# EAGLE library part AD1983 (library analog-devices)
HD Audio SoundMAX® Codec Auto generated by make-symbol-device-package-bsdl.ulp Rev. 33 Source: http://www.analog.com/static/imported-files/data_sheets/AD1983.pdf
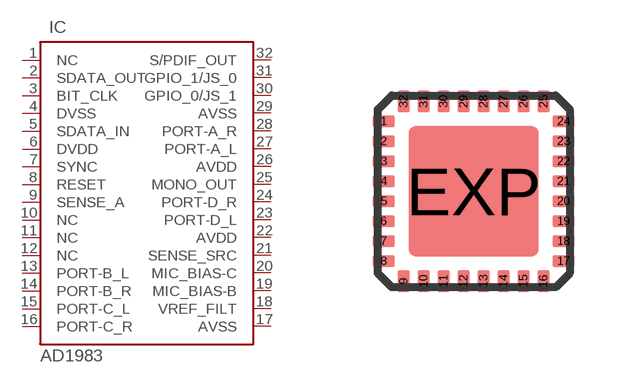
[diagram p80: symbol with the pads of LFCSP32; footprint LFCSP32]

Designator prefix IC

## AD1983 (OC_FARNELL: unknown; OC_NEWARK: unknown)  [LFCSP32]
1  NC  nc
2  SDATA_OUT  in
3  BIT_CLK  in
4  DVSS  pwr
5  SDATA_IN
6  DVDD  pwr
7  SYNC  in
8  RESET  in
9  SENSE_A  in
10  NC  nc
11  NC  nc
12  NC  nc
13  PORT-B_L  in
14  PORT-B_R  in
15  PORT-C_L  in
16  PORT-C_R  in
17  AVSS  pwr
18  VREF_FILT  out
19  MIC_BIAS-B  out
20  MIC_BIAS-C  out
21  SENSE_SRC  out
22  AVDD  pwr
23  PORT-D_L  out
24  PORT-D_R  out
25  MONO_OUT  out
26  AVDD  in
27  PORT-A_L  out
28  PORT-A_R  out
29  AVSS  pwr
30  GPIO_0/JS_1
31  GPIO_1/JS_0
32  S/PDIF_OUT  out

## Footprint LFCSP32 (pad centres in mm)
32-Lead Frame Chip Scale Package [LFCSP_VQ] 5 mm × 5 mm Very Thin Quad (CP-32-3 COMPLIANT TO JEDEC STANDARDS MO-220-VHHD-2 Source: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
smd 0.55 x 0.3: 1 -2.25,1.75; 2 -2.25,1.25; 3 -2.25,0.75; 4 -2.25,0.25; 5 -2.25,-0.25; 6 -2.25,-0.75; 7 -2.25,-1.25; 8 -2.25,-1.75; 17 2.25,-1.75; 18 2.25,-1.25; 19 2.25,-0.75; 20 2.25,-0.25; 21 2.25,0.25; 22 2.25,0.75; 23 2.25,1.25; 24 2.25,1.75
smd 0.3 x 0.55: 9 -1.75,-2.25; 10 -1.25,-2.25; 11 -0.75,-2.25; 12 -0.25,-2.25; 13 0.25,-2.25; 14 0.75,-2.25; 15 1.25,-2.25; 16 1.75,-2.25; 25 1.75,2.25; 26 1.25,2.25; 27 0.75,2.25; 28 0.25,2.25; 29 -0.25,2.25; 30 -0.75,2.25; 31 -1.25,2.25; 32 -1.75,2.25
smd 3.25 x 3.25: EXP 0,0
